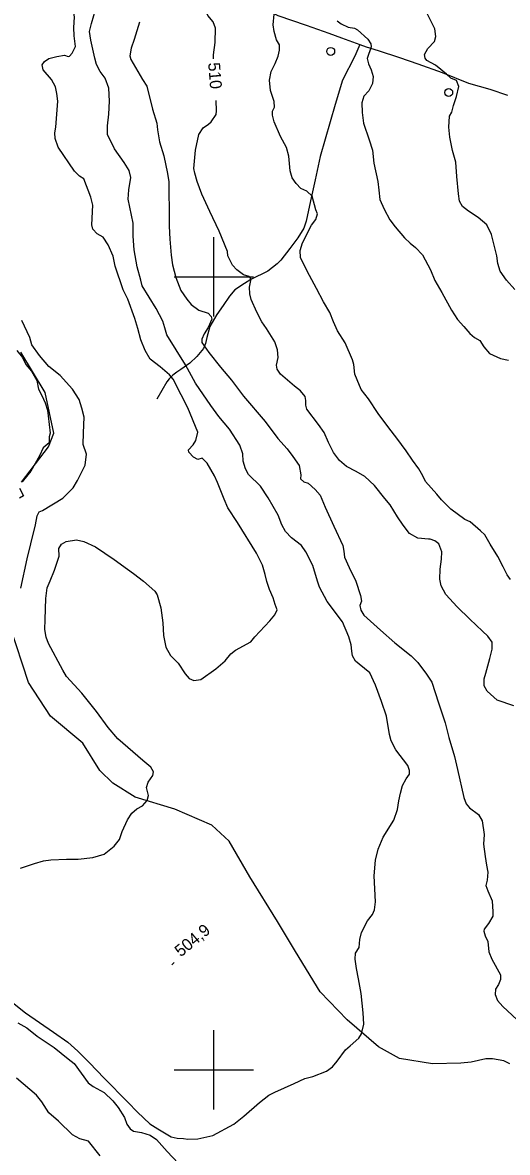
# Model space of a CAD drawing. Extents: x 347059 to 352153, y 6073752 to 6078601.
# Drawn here: x 349727.6 to 349911.2, y 6077068.8 to 6077496.2 of the extents above; entities that cross this region are included whole.
import ezdxf

# ---------------------------------------------------------------- set-up
doc = ezdxf.new("R2010")
doc.units = 0
for name, color, linetype in [('Level 1', 7, 'Continuous'), ('Level 2', 7, 'Continuous'), ('Level 22', 7, 'Continuous'), ('Level 3', 7, 'Continuous'), ('Level 36', 7, 'Continuous'), ('Level 4', 7, 'Continuous'), ('Level 44', 7, 'Continuous'), ('Level 61', 7, 'Continuous')]:
    doc.layers.add(name, color=color, linetype=linetype)

msp = doc.modelspace()

# ---------------------------------------------------------------- linework, layer by layer
at = {"layer": 'Level 1'}
for points in [[(349799.91, 6077482.56), (349799.84, 6077483.99), (349800.45, 6077488.63), (349800.62, 6077494.11), (349799.75, 6077496.46), (349797.78, 6077498.84), (349797.24, 6077500.14), (349797.5, 6077501.29), (349798.2, 6077502.4), (349798.36, 6077503.19), (349799.27, 6077508.15), (349796.43, 6077510.55), (349795.88, 6077511.7), (349795.69, 6077512.74), (349797.91, 6077516.57), (349800.07, 6077524.21), (349801.04, 6077529.55), (349803.16, 6077535.29), (349804.42, 6077541.4), (349806.34, 6077548.85), (349807.63, 6077553.65), (349808.42, 6077557.9), (349810.41, 6077564.61)], [(349806.14, 6077406.15), (349805.29, 6077407.99), (349805.15, 6077409.61), (349802.01, 6077417.31), (349798.54, 6077424.74), (349795.51, 6077431.33), (349793.62, 6077436.05), (349792.75, 6077439.21), (349792.42, 6077441.07), (349793.03, 6077447.98), (349794.29, 6077453.94), (349796.01, 6077456.42), (349797.98, 6077457.78), (349798.96, 6077458.71), (349800.92, 6077461.39), (349801.06, 6077462.84), (349800.9, 6077466.75)], [(349913.61, 6077237.7), (349907.32, 6077239.91), (349903.51, 6077243.21), (349902.38, 6077245.23), (349902.43, 6077247.94), (349903, 6077250.02), (349904.52, 6077255.67), (349905.39, 6077259.19), (349905.36, 6077261.83), (349903.8, 6077264.03), (349901.7, 6077265.92), (349896.91, 6077270.56), (349892.19, 6077275.12), (349887.86, 6077279.86), (349886.11, 6077283.11), (349885.62, 6077285.65), (349885.77, 6077289.38), (349886.15, 6077293.16), (349886.35, 6077296), (349885.25, 6077298.97), (349883.74, 6077300.14), (349881.96, 6077300.82), (349881.29, 6077300.81), (349877.19, 6077301.2), (349874.12, 6077302.96), (349871.69, 6077306.05), (349869.57, 6077309.26), (349866.77, 6077313.78), (349864.71, 6077316.1), (349860.85, 6077321.08), (349857.12, 6077324.44), (349853.92, 6077326.36), (349850.27, 6077328.32), (349847.62, 6077330.55), (349845.34, 6077333.62), (349843.43, 6077337.4), (349841.72, 6077341.08), (349839.67, 6077344.2), (349835.22, 6077349.9), (349834.86, 6077351.48), (349834.89, 6077353.23), (349834.59, 6077354.73), (349832.81, 6077356.88), (349830.49, 6077358.71), (349825.18, 6077363.17), (349823.97, 6077365.11), (349823.75, 6077366.67), (349824.33, 6077369.55), (349824.1, 6077372.43), (349823.08, 6077375.46), (349819.96, 6077380.52), (349818.15, 6077383.04), (349816.22, 6077386.66), (349814.12, 6077391.48), (349813.59, 6077393.58), (349813.54, 6077396.08), (349814.09, 6077399.32), (349813.36, 6077400.2), (349811.21, 6077400.84), (349808.66, 6077402.62), (349807.07, 6077404.38), (349806.14, 6077406.15)], [(349756.99, 6077067.52), (349752.5, 6077073.06), (349749.3, 6077073.95), (349746.48, 6077075.45), (349741.15, 6077080.57), (349737.47, 6077083.77), (349734.83, 6077087.88), (349732.9, 6077090.47), (349725.22, 6077096.89)]]:
    msp.add_lwpolyline(points, dxfattribs=at)
at = {"layer": 'Level 2'}
for points in [[(349735.04, 6077480.22), (349735.84, 6077481.54), (349737.5, 6077482.64), (349740.53, 6077483.39), (349743.47, 6077483.93), (349744.82, 6077483.44), (349745.34, 6077483.46), (349746.35, 6077484.69), (349747.64, 6077487.22), (349747.07, 6077491.17), (349746.94, 6077494.42), (349747.17, 6077498.23), (349746.92, 6077500.16), (349746.2, 6077503.32), (349746.47, 6077505.28), (349747.08, 6077506.99), (349750.18, 6077511.42), (349750.87, 6077513.19), (349750.33, 6077515.16), (349748.7, 6077516.63), (349743.88, 6077517.11), (349743.72, 6077517.57)], [(349829.46, 6077301.22), (349827.12, 6077303.72), (349825.74, 6077306.21), (349824.32, 6077309.87), (349820.53, 6077316.41), (349817.71, 6077320.79), (349813.12, 6077325.2), (349811.94, 6077327.44), (349811.1, 6077330.24), (349811.02, 6077333.12), (349809.86, 6077336.32), (349805.88, 6077342.43), (349801.92, 6077347.21), (349798.92, 6077351.32), (349793.03, 6077359.74), (349789.22, 6077366.79), (349782.2, 6077378.03), (349781.5, 6077380.67), (349780.72, 6077383.24), (349778.1, 6077388.04), (349772.89, 6077396.62), (349772.29, 6077398.8), (349771.01, 6077403.77), (349769.81, 6077410.28), (349769.5, 6077415.38), (349769.41, 6077420.39), (349767.49, 6077429.38), (349767.77, 6077432.96), (349768.61, 6077437.66), (349767.91, 6077440.3), (349765.98, 6077443.27), (349762.36, 6077448.45), (349759.73, 6077453.92), (349759.75, 6077457.15), (349760.19, 6077461.52), (349760.53, 6077466.48), (349760.27, 6077471.35), (349758.81, 6077475.24), (349756.99, 6077477.76), (349755.55, 6077480.31), (349754.9, 6077482.73), (349753.37, 6077489.63), (349752.96, 6077492.9), (349753.7, 6077495.92), (349755.47, 6077501.92)], [(349825.22, 6077453.16), (349822.9, 6077458.72), (349822.19, 6077461.2), (349822.27, 6077462.73), (349823.01, 6077464.27), (349822.85, 6077466.41), (349821.49, 6077470.49), (349821.07, 6077474.41), (349821.69, 6077477.72), (349823.24, 6077480.72), (349824.4, 6077483.54), (349824.85, 6077485.77), (349824.82, 6077487.75), (349823.76, 6077489.68), (349822.89, 6077492.83), (349822.41, 6077495.37), (349822.9, 6077499.4)], [(349914.02, 6077395.23), (349910.83, 6077398.74), (349908.44, 6077402.11), (349907.49, 6077405.04), (349907.19, 6077407.99), (349905.19, 6077416.07), (349903.35, 6077419.75), (349900.16, 6077422.46), (349896.43, 6077424.85), (349894.18, 6077426.59), (349893.05, 6077428.6), (349892.67, 6077431.48), (349892.07, 6077438.04), (349891.65, 6077443.41), (349890.32, 6077447.77), (349889.35, 6077452.83), (349888.99, 6077456.66), (349889.26, 6077460.87), (349890.07, 6077462.33), (349890.77, 6077464.89), (349891.84, 6077468.3), (349892.8, 6077472.01), (349891.85, 6077474.29), (349889.73, 6077475.22), (349888.14, 6077476.65), (349885.94, 6077478.49), (349883.96, 6077480.06), (349880.61, 6077481.83), (349879.97, 6077482.76), (349879.8, 6077484.09), (349881.07, 6077486.46), (349883.53, 6077489.01), (349884.02, 6077491.01), (349883.71, 6077493.81), (349879.91, 6077501.47)], [(349771.83, 6077496.35), (349769.85, 6077489.78), (349768.72, 6077486.58), (349768.14, 6077483.7), (349768.52, 6077482.27), (349773.01, 6077474.74), (349774.6, 6077472.17), (349776.83, 6077463.45), (349778.37, 6077458.17), (349778.71, 6077455.65), (349779.37, 6077451.11), (349781.06, 6077445.81), (349782.39, 6077439.16), (349782.97, 6077436.02), (349783.01, 6077432.72), (349783.09, 6077424.63), (349783.14, 6077419.2), (349783.32, 6077414.26)], [(349846.74, 6077496.89), (349848.18, 6077495.81), (349850.85, 6077494.54), (349853.23, 6077494.1), (349854.42, 6077493.48), (349858.33, 6077489.9), (349859.41, 6077488.12), (349859.56, 6077487.06), (349858.05, 6077482.62), (349858.51, 6077480.6), (349859.54, 6077478.38), (349860.32, 6077475.83), (349860.06, 6077473.22), (349858.67, 6077470.35), (349856.85, 6077468.32), (349856.09, 6077465.83), (349856.17, 6077462.17), (349856.66, 6077458.17), (349858.83, 6077451.83), (349860.14, 6077447.98), (349860.6, 6077443.04), (349862.05, 6077436.1), (349862.53, 6077432.77), (349862.85, 6077429.3), (349864.46, 6077425.57), (349866.65, 6077421.63), (349868.66, 6077418.89), (349872.16, 6077414.83), (349874.39, 6077412.79)], [(349795.02, 6077247.73), (349800.81, 6077251.67), (349804.31, 6077254.8), (349806.41, 6077257.33), (349808.26, 6077258.84), (349814.06, 6077261.97), (349815.5, 6077263.83), (349821.14, 6077269.92), (349823.13, 6077272.09), (349823.92, 6077274.08), (349823.23, 6077276.06), (349822.51, 6077278.56), (349821.12, 6077281.71), (349820.09, 6077284.75), (349819.47, 6077287.46), (349818.4, 6077290.88), (349816.19, 6077295.51), (349808.9, 6077307.1), (349805.29, 6077312.6), (349803.92, 6077315.89), (349801.43, 6077322.17), (349800.27, 6077324.71), (349797.41, 6077329.47), (349795.53, 6077331.41), (349793.93, 6077330.9), (349792.24, 6077331.8), (349790.57, 6077333.65), (349790.45, 6077334.62), (349792.12, 6077336.52), (349793.24, 6077338.11), (349793.91, 6077341.21), (349790.17, 6077350.47), (349787.61, 6077355.35), (349784.58, 6077361.31), (349783.26, 6077362.9), (349779.72, 6077366.03), (349775.92, 6077368.82), (349773.96, 6077372.17), (349772.37, 6077376.22), (349771.24, 6077380.52), (349770.13, 6077384.3), (349767.37, 6077391.55), (349765.65, 6077395.1), (349762.69, 6077404.06), (349761.88, 6077407.82), (349760.02, 6077412.19), (349758.08, 6077415.02), (349755.84, 6077416.26), (349754.18, 6077418.11), (349753.75, 6077419.76), (349754.11, 6077427.16), (349753.37, 6077430.18), (349750.73, 6077437.12), (349749.13, 6077438.08), (349747.25, 6077440.02), (349741.06, 6077449.13), (349739.89, 6077452.33), (349739.74, 6077454.47), (349740.18, 6077456.71), (349740.86, 6077466.51), (349740.48, 6077469.42), (349739.99, 6077471.96), (349738.49, 6077474.75), (349735.38, 6077478.35), (349735.04, 6077480.22)], [(349912.33, 6077285.52), (349911.11, 6077287.33), (349909.56, 6077290.33), (349907.58, 6077294.18), (349904.58, 6077298.94), (349902.64, 6077302.42), (349900.95, 6077303.97), (349897.08, 6077307.34), (349895.1, 6077308.26), (349889.73, 6077312.14), (349886.25, 6077315.69), (349884.39, 6077317.77), (349880.15, 6077322.57), (349879.18, 6077324.71), (349877.67, 6077327.35), (349875.2, 6077330.66), (349872.82, 6077334.18), (349869.24, 6077338.98), (349866.24, 6077342.93), (349862.2, 6077348.29), (349858.55, 6077353.83), (349855.81, 6077357.46), (349854.32, 6077361.04), (349853.44, 6077363.25), (349852.99, 6077366.88), (349852.57, 6077368.67), (349849.67, 6077375.1), (349846.8, 6077379.54), (349845.3, 6077382.98), (349843.88, 6077386.48), (349841.56, 6077390.58), (349838.89, 6077395.59), (349836.28, 6077400.52), (349833.79, 6077405.14), (349832.83, 6077407.28), (349832.65, 6077409.93), (349833.6, 6077412.85), (349836.92, 6077419.57), (349838.61, 6077421.75), (349839.26, 6077423.89), (349838.67, 6077425.41), (349837.29, 6077430.53), (349835.17, 6077432.4), (349832.98, 6077433.4), (349831.19, 6077435.4), (349829.71, 6077437.52), (349828.93, 6077440.08), (349828.38, 6077445.62), (349827.53, 6077448.92), (349825.22, 6077453.16)], [(349783.32, 6077414.26), (349783.83, 6077408.27), (349784.35, 6077404.55), (349785.58, 6077399.81), (349787.44, 6077394.8), (349789.71, 6077391.58), (349791.35, 6077389.59), (349794.32, 6077387.47), (349797.82, 6077386.34), (349799.02, 6077385.05), (349799.21, 6077384.01), (349797.79, 6077380.84), (349796.38, 6077378.47), (349795.45, 6077376.5), (349795.46, 6077375.18), (349798.04, 6077371.42), (349802.51, 6077365.86), (349806.68, 6077360.99), (349811.24, 6077354.83), (349819.38, 6077345.33), (349824.2, 6077338.85), (349827.73, 6077334.92), (349829.96, 6077332.07), (349832.27, 6077328.62), (349832.89, 6077325.11), (349832.81, 6077323.57), (349834.03, 6077322.43), (349835.75, 6077321.97), (349838.4, 6077319.59), (349840.25, 6077317.36), (349842.17, 6077312.92), (349845.45, 6077305.71), (349848.86, 6077298.33), (349849.24, 6077296.24), (349849.46, 6077294.01), (349851.22, 6077290.1), (349853.81, 6077284.86), (349855.56, 6077279.48), (349855.95, 6077277.38), (349855.33, 6077275.68), (349855.68, 6077273.95), (349856.83, 6077272.08), (349863.06, 6077266.35), (349868.5, 6077261.57), (349874.75, 6077256.64), (349877.23, 6077254.12), (349880.57, 6077249.76), (349882.56, 6077246.7), (349885.12, 6077238.89), (349887.62, 6077231.3), (349888.99, 6077225.73), (349891.17, 6077218.54), (349892.3, 6077213.58), (349894.73, 6077202.98), (349895.54, 6077200.7), (349896.8, 6077199.18), (349900.25, 6077196.65), (349901.56, 6077194.24), (349902.38, 6077189.02), (349902.16, 6077185.36), (349902.74, 6077180.75), (349903.22, 6077177.39), (349903.78, 6077174.76), (349903.56, 6077171.77), (349902.98, 6077169.69)], [(349874.39, 6077412.79), (349876.35, 6077411.07), (349879.02, 6077408.34), (349882.08, 6077402.71), (349883.73, 6077398.61), (349886.3, 6077394.05), (349890.06, 6077387.41), (349892.29, 6077383.91), (349894.67, 6077381.2), (349896.99, 6077378.57), (349898.76, 6077377.09), (349900.78, 6077375.95), (349902.24, 6077373.54), (349904.34, 6077371), (349908.5, 6077369.08), (349911.62, 6077368.56)], [(349726.86, 6077282.25), (349729.36, 6077293.28), (349730.74, 6077298.98), (349732.49, 6077306.18), (349733.05, 6077309.59), (349733.86, 6077311.06), (349735.11, 6077311.68), (349742.82, 6077316.26), (349746.76, 6077320.16), (349748.37, 6077322.95), (349751.24, 6077328.8), (349751.74, 6077332.97), (349750.46, 6077336.61), (349750.6, 6077341.02), (349750.89, 6077346.89), (349750.04, 6077350.36), (349748.96, 6077353.63), (349746.45, 6077357.48), (349741.86, 6077362.7), (349737.46, 6077366.06), (349733.95, 6077370.3), (349731.02, 6077374.33), (349730.25, 6077377.06), (349727.34, 6077383.52)], [(349726.83, 6077176.25), (349732.04, 6077178.1), (349735.46, 6077179.02), (349738.23, 6077179.41), (349744.18, 6077179.73), (349748.62, 6077179.74), (349754.22, 6077180.3), (349758.42, 6077181.59), (349762.27, 6077184.61), (349764.22, 6077187.14), (349765.34, 6077190.2), (349767.33, 6077194.65), (349768.91, 6077197.15), (349770.84, 6077198.73), (349773.03, 6077199.84), (349774.71, 6077201.89), (349775.19, 6077203.76), (349774.53, 6077206.84), (349775.18, 6077208.84), (349776.9, 6077211.32), (349777.19, 6077212.77), (349776.11, 6077214.57), (349773.1, 6077217.06), (349763.7, 6077225.18), (349759.98, 6077229.51), (349755.55, 6077235.53), (349750.03, 6077242.53), (349744.14, 6077248.83), (349742.83, 6077251.24), (349737.39, 6077261.25), (349736.53, 6077263.76), (349735.99, 6077266.54), (349736.07, 6077270.35), (349736.35, 6077278.35), (349736.9, 6077282.42), (349737.97, 6077285.04), (349739.63, 6077289.07), (349741.48, 6077294.34), (349741.33, 6077297.3), (349742.3, 6077298.9), (349744.03, 6077299.92), (349747.94, 6077300.58), (349750.76, 6077299.94), (349755.21, 6077297.83), (349762.21, 6077293.11), (349767.25, 6077289.47), (349769.6, 6077287.78), (349773.38, 6077284.84), (349777.67, 6077281.12), (349778.57, 6077279.71), (349779.93, 6077274.79), (349780.7, 6077269.13), (349780.97, 6077264.39), (349781.79, 6077259.97), (349783.62, 6077256.77), (349786.44, 6077253.85), (349789.15, 6077249.77), (349790.68, 6077248.07), (349792.39, 6077247.32), (349795.02, 6077247.73)], [(349793.91, 6077073.85), (349799.58, 6077075.13), (349807.56, 6077079.5), (349811.33, 6077082.45), (349817.25, 6077087.68), (349820.78, 6077090.42), (349823.11, 6077091.52), (349830.39, 6077094.79), (349834.5, 6077096.67), (349837.47, 6077097.48), (349842.63, 6077099.55), (349844.94, 6077101.17), (349846.7, 6077103.28), (349849.87, 6077107.61), (349851.64, 6077109.05), (349854.9, 6077111.98), (349855.87, 6077113.57), (349856.83, 6077117.31), (349856.58, 6077121.53), (349855.76, 6077128.89), (349854.83, 6077134.43), (349854.03, 6077138.33), (349853.56, 6077141.84), (349853.65, 6077144.18), (349855.08, 6077146.31), (349855.26, 6077149.25), (349855.89, 6077151.91), (349858.18, 6077156.33), (349860.06, 6077158.8), (349860.82, 6077160.49), (349861.27, 6077163.54), (349860.77, 6077173.45), (349861.2, 6077179.29), (349862.21, 6077183.47), (349864.07, 6077188.07), (349868.19, 6077194.52), (349869.54, 6077198.44), (349870.02, 6077201.78), (349870.69, 6077204.73), (349871.48, 6077207.53), (349872.77, 6077210.05), (349874.13, 6077211.84), (349874.13, 6077213.31), (349873.42, 6077215.14), (349868.97, 6077221.02), (349867.16, 6077224.5), (349866.51, 6077226.92), (349865.42, 6077233.79), (349863.52, 6077239.35), (349861.25, 6077245.52), (349859.04, 6077250.15), (349855.07, 6077253.47), (349853.63, 6077254.57), (349852.5, 6077256.59), (349852.23, 6077258.38), (349851.95, 6077260.83), (349851.14, 6077263.78), (349848.67, 6077269.53), (349842.91, 6077277.14), (349839.98, 6077282.64), (349839.31, 6077284.91), (349837.53, 6077290.82), (349834.78, 6077295.94), (349833.17, 6077298.37), (349829.46, 6077301.22)], [(349902.98, 6077169.69), (349903.82, 6077167.7), (349905.44, 6077163.94), (349905.69, 6077159.73), (349905.61, 6077158.19), (349904.01, 6077155.41), (349902.39, 6077153.28), (349902.3, 6077152.41), (349902.8, 6077150.67), (349903.7, 6077148.6), (349904.12, 6077144.66), (349905.25, 6077141.83), (349908.52, 6077135.93), (349908.57, 6077134.23), (349907.86, 6077132.31), (349906.65, 6077130.52), (349906.59, 6077128.47), (349907.4, 6077126.18), (349909.48, 6077123.99), (349916.66, 6077117.27)], [(349721.82, 6077126.95), (349728.67, 6077121.59), (349739.24, 6077114.31), (349744.7, 6077110.48), (349748.49, 6077107.02), (349752.87, 6077102.7), (349758.41, 6077096.79), (349767.43, 6077087.83), (349771.11, 6077084.02), (349775.7, 6077079.6), (349778.76, 6077077.68), (349783.79, 6077074.69), (349786.17, 6077074.09), (349788.53, 6077074.01), (349790.2, 6077073.77), (349793.91, 6077073.85)], [(349725.72, 6077117.8), (349729.15, 6077115.93), (349733.11, 6077112.76), (349739.47, 6077108.47), (349744.87, 6077104.2), (349747.05, 6077102.38), (349752.37, 6077095.11), (349754.3, 6077093.75), (349758.5, 6077091.43), (349761.73, 6077088.32), (349763.76, 6077085.7), (349766.19, 6077081.94), (349767.05, 6077079.44), (349768.28, 6077077.63), (349769.52, 6077076.78), (349772.64, 6077076.25), (349775.94, 6077075.34), (349778.29, 6077073.64), (349782.33, 6077069.06), (349786.48, 6077064.69)]]:
    msp.add_lwpolyline(points, dxfattribs=at)
at = {"layer": 'Level 22'}
for points in [[(349762.58, 6077526.33), (349765.01, 6077524.56), (349768.69, 6077522.52), (349775.33, 6077518.73), (349783.91, 6077513.34), (349791.96, 6077509.93), (349796.49, 6077508.39), (349802.54, 6077507.37), (349806.1, 6077506.98), (349811.97, 6077505.36), (349817.78, 6077502.11), (349824.28, 6077498.92), (349834.9, 6077495.3), (349843.57, 6077492.21), (349848.31, 6077490.41), (349855.31, 6077487.89), (349857.64, 6077487.06), (349862.25, 6077485.68), (349870.37, 6077482.97), (349877.24, 6077480.57), (349886.49, 6077477.32), (349896.47, 6077473.35), (349904.57, 6077471.01), (349911.2, 6077468.72)], [(349855.31, 6077487.89), (349853.45, 6077483.51), (349848.72, 6077474.43), (349845.94, 6077465.26), (349840.22, 6077445.5), (349838.33, 6077436.71), (349836.56, 6077428.84), (349835.02, 6077421.15), (349834.04, 6077418.45), (349831.79, 6077414.76), (349828.78, 6077410.8), (349825.32, 6077406.31), (349823.97, 6077404.96), (349820.41, 6077402.19), (349813.95, 6077399.03), (349811.56, 6077397.47), (349807.99, 6077395.07), (349805.98, 6077392.71), (349803.58, 6077389.18), (349801.1, 6077385.74), (349798.45, 6077381.26), (349797.38, 6077377.04), (349796.85, 6077374.79), (349796.03, 6077372.97), (349793.58, 6077369.86), (349790.85, 6077367.34), (349787.52, 6077364.92), (349786.04, 6077363.98), (349784.46, 6077362.88), (349783.1, 6077361.43), (349782.18, 6077360.36), (349778.39, 6077353.77)]]:
    msp.add_lwpolyline(points, dxfattribs=at)
at = {"layer": 'Level 3'}
msp.add_line((349784.11, 6077139.79), (349785.03, 6077140.56), dxfattribs=at)
at = {"layer": 'Level 36'}
for centre in [(349844.25, 6077485.33), (349888.94, 6077469.76)]:
    msp.add_circle(centre, 1.5, dxfattribs=at)
at = {"layer": 'Level 4'}
for points in [[(349725.42, 6077372.14), (349727.58, 6077369.56), (349728.82, 6077366.81), (349730.95, 6077364.28), (349732.99, 6077360.84), (349733.64, 6077357.53), (349734.84, 6077355.19), (349736.1, 6077352.32), (349737.05, 6077349.56), (349737.24, 6077347.44), (349738.01, 6077340.89), (349737.68, 6077339.48), (349737.64, 6077337.17), (349735.42, 6077335.3), (349733.95, 6077332.25), (349730.68, 6077326.47), (349727.36, 6077322.47)], [(349726.37, 6077320.12), (349727.92, 6077317.18), (349726.44, 6077316.32)], [(349912.09, 6077102.28), (349909.82, 6077103.4), (349905.56, 6077104.22), (349902.97, 6077104.18), (349897.46, 6077102.95), (349893.48, 6077102.48), (349882.82, 6077102.25), (349870.3, 6077104.24), (349862.34, 6077108.69), (349850.47, 6077118.9), (349840.27, 6077129.46), (349830.97, 6077144.71), (349824.12, 6077156.14), (349813.57, 6077173.06), (349805.74, 6077186.55), (349799.22, 6077192.54), (349785.22, 6077198.6), (349770.19, 6077203.19), (349761.8, 6077208.52), (349756.79, 6077213.23), (349750.4, 6077223.57), (349738.16, 6077233.85), (349729.75, 6077246.59), (349722.83, 6077267.69)]]:
    msp.add_lwpolyline(points, dxfattribs=at)
at = {"layer": 'Level 44'}
msp.add_lwpolyline([(349727.21, 6077322.29), (349737.37, 6077335.66), (349739.4, 6077340.85), (349736.07, 6077356.22), (349726.89, 6077371.53)], dxfattribs=at)
at = {"layer": 'Level 61'}
for p, q in [((349800, 6077385), (349800, 6077415)), ((349785, 6077400), (349815, 6077400)), ((349800, 6077085), (349800, 6077115)), ((349785, 6077100), (349815, 6077100))]:
    msp.add_line(p, q, dxfattribs=at)

# ---------------------------------------------------------------- texts
at = {"layer": 'Level 1'}
msp.add_text('510', height=4.5, rotation=274.5997, dxfattribs=at).set_placement((349797.82, 6077480.95))
at = {"layer": 'Level 3'}
msp.add_text('504,9', height=4.5, rotation=39.62, dxfattribs=at).set_placement((349787.47, 6077142.5))

doc.saveas('drawing.dxf')
